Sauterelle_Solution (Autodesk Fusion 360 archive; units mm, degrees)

design "Sauterelle" references "Axe_Placage", "Embase", "Poignee", "Axe", "Support_placage", "Bielette"
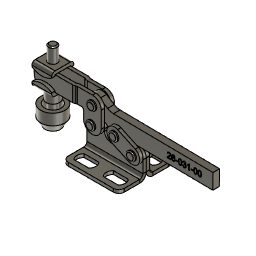
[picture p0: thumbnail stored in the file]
parameter "d13" = 1.5
parameter "d14" = 1.5
parameter "d40" = 1.5
component_insert "Insertion d'un composant1"
ground "Terre1"
component_insert "Insertion d'un composant2"
component_insert "Insertion d'un composant3"
component_insert "Insertion d'un composant4"
component_insert "Insertion d'un composant5"
component_insert "Insertion d'un composant6"
component_insert "Insertion d'un composant7"
component_insert "Insertion d'un composant8"
joint "Assembler1" alignAngle 0 alignOffsetX 0 alignOffsetY 0 alignOffsetZ 0
joint "Assembler2" alignAngle 0 alignOffsetX 0 alignOffsetY 0 alignOffsetZ 0
joint "Assembler3" alignAngle 0 alignOffsetX 0 alignOffsetY 0 alignOffsetZ 0
work_axis "Axe de construction1"
work_axis "Axe de construction2"
work_plane "Plan de construction3"
work_plane "Plan de construction1" AlongDistance -15.5 (= "( -31 / 2 ) * 1 mm")
sketch "Esquisse1" plane through (-24.25, -2.25, 16.25) normal (1, 0, 0) x axis (0, 1, 0)
  line L1 (5.75, 0.75) -> (4.25, 0.75)
  line L2 (5.75, 7.75) -> (5.75, 0.75)
  line L3 (4.25, 7.75) -> (5.75, 7.75)
  line L4 (5.75, 7.75) -> (5.75, 5.75)
  line L5 (-1.25, 7.75) -> (5.75, 7.75)
  line L6 (-1.25, 5.75) -> (-1.25, 7.75)
  line L7 (0.75, 13.9643) -> (0.75, 7.0307)
  line L8 (3.75, 7.0307) -> (3.75, 13.9643)
  line L9 (2.25, 14.1414) -> (2.25, 7.75)
  point P6 (5.75, 5.75)
  point P5 (5.75, 7.75)
  point P7 (5.75, 7.75)
  point P8 (5.75, 7.75)
  point P11 (-1.25, 5.75)
  point P9 (-1.25, 7.75)
  point P10 (-1.25, 7.75)
  point P16 (2.25, 7.75)
  coincident L2 P6
  coincident P5 P7
  perpendicular L3 L4
  coincident P5 P8
  perpendicular L5 L6
  horizontal P6 P11
  coincident P9 P10
  midpoint L5 P16
  perpendicular L5 L9
  dimension "d16" distance P6 L5 = 2
extrude "Extrusion1" new body distance 9 Side1WallThickness 1.5
fillet "Congé" radius 1.5
sketch "Esquisse2" plane through (0, -5, 0) normal (0, -1, 0) x axis (1, 0, 0)
  line L1 (-28.75, 24) -> (-19.75, 24)
  line L2 (-28.75, 22) -> (-28.75, 24)
  line L3 (-19.75, 22) -> (-28.75, 22)
  line L4 (-19.75, 24) -> (-19.75, 22)
  circle C1 centre (-24.25, 30) radius 8
  point P7 (-24.25, 22)
  point P6 (-24.25, 30)
  tangent L3 C1
  midpoint L3 P7
  vertical P6 P7
  dimension "d22" diameter C1 = 16
extrude "Extrusion2" sketch "Esquisse2" profile of L1 L2 L4 C1 no distance stored
sketch "Esquisse3" plane through (0, 0, 25.5) normal (0, 0, 1) x axis (-1, 0, 0)
  line L1 (28.75, -3.5) -> (19.75, -3.5)
  line L2 (28.75, 3.5) -> (28.75, -3.5)
  line L3 (19.75, 3.5) -> (28.75, 3.5)
  line L4 (19.75, -3.5) -> (19.75, 3.5)
  line L5 (19.75, 3.5) -> (28.75, -3.5)
  point P3 (28.75, -3.5)
  point P6 (28.75, -3.5)
  point P5 (19.75, 3.5)
  point P7 (19.75, 3.5)
  point P8 (24.25, 0)
  coincident P3 P6
  coincident P5 P7
  midpoint L5 P8
hole "Perçage" HoleDepth 3.23 HoleDiameter 4 TipAngle 180
work_plane "Plan de construction2"
mirror "Symétrie miroir" mirrorStitchTolerance 0.1
sketch "Esquisse4" plane through (0, 0, 15.5) normal (0, 0, -1) x axis (1, 0, 0)
  line L1 (-19.75, -3.5) -> (-28.75, -3.5)
  line L2 (-19.75, 3.5) -> (-19.75, -3.5)
  line L3 (-28.75, 3.5) -> (-19.75, 3.5)
  line L4 (-28.75, -3.5) -> (-28.75, 3.5)
  circle C1 centre (-24.25, 0) radius 2
  circle C2 centre (-24.25, 0) radius 3
  concentric C1 C2
  dimension "d29" diameter C2 = 6
extrude "Extrusion3" add sketch "Esquisse4" profile of C1 C2 along normal blind 5
thread "Filetage"
component_from_bodies "Corps->Comp1"
component_from_bodies "Corps->Comp2"
component_insert "Insertion d'un composant9"
base_feature "Fonction de base1"
joint "Assembler23" alignAngle 0 alignOffsetX 0 alignOffsetY 0 alignOffsetZ 0
joint "Assembler24" alignAngle 0 alignOffsetX 0 alignOffsetY 0 alignOffsetZ 0 DistanceMinimum -12.5 DistanceMaximum -5.5
joint "Assembler25" alignAngle 0 alignOffsetX 0 alignOffsetY 0 alignOffsetZ 0 AngleRest 0
motion_link "MotionLink7" Value1 10 Value2 360
joint "Assembler26" alignAngle 0 alignOffsetX 0 alignOffsetY 0 alignOffsetZ 0
joint "Assembler27" alignAngle 0 alignOffsetX 0 alignOffsetY 0 alignOffsetZ 0
joint "Assembler28" alignAngle 0 alignOffsetX 0 alignOffsetY 0 alignOffsetZ 0
component_insert "Insertion d'un composant11"
joint "Assembler29" alignAngle 0 alignOffsetX 0 alignOffsetY 0 alignOffsetZ 0
joint "Assembler30" alignAngle 0 alignOffsetX 0 alignOffsetY 0 alignOffsetZ 0
joint "Assembler31" alignAngle 0 alignOffsetX 0 alignOffsetY 0 alignOffsetZ 0
mirror_component "MirrorComponent2"
derived_instance "DerivedInstance10"
derived_instance "DerivedInstance11"
derived_instance "DerivedInstance1"
derived_instance "DerivedInstance1"
ground "Terre22"
as_built_joint "Réelle"
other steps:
step "Āᶇ    ́   Ā䣧乸攝햽␀ 䔀㌰㠷䔴ⵄ䔵㤱㐭ㅅⴴ㥂㉆㌭あ〷㜱㄰䌸D谁    Ā    硈ᵎ뵥Õ$ 〹䘴㠸䔵䐭㔸ⴹ㜴㔵䄭䔷ⵆ䔶䕂㡄㌷䘲䑁Ā"
derived_base_feature "Fonction de base dérivée1"
derived_base_feature "Fonction de base dérivée1"
derived_base_feature "Fonction de base dérivée1"
base_feature "Fonction de base1"
base_feature "Fonction de base1"
create_component "CreateComponent4"
remove_body "RemoveBody1"
create_component "CreateComponent5"
remove_body "RemoveBody2"
create_component "CreateComponent6"
joint_origin "JointOrigin2"
joint_origin "JointOrigin4"
joint_origin "JointOrigin3"
create_component "CreateComponent17"
create_component "CreateComponent18"
create_component "CreateComponent19"

design "Squelette"
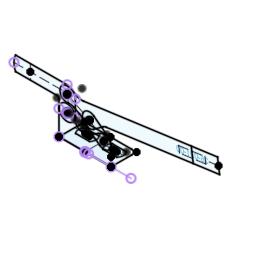
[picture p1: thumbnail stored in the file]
parameter "d71" = 3 (= "Linear Dimension-10")
sketch "Esquisse1" plane through (0, 0, 0) normal (0, 0, 1) x axis (1, 0, 0)
  line L1 (12.75, 0) -> (-12.75, 0)
  line L2 (-12.75, 10) -> (-12.75, 0)
  line L3 (10.25, 12.5) -> (-10.25, 12.5)
  line L4 (12.75, 0) -> (12.75, 10)
  line L5 (12.75, 7.8) -> (-12.75, 7.8)
  line L6 (0, 0) -> (0, 12.5)
  line L7 (-3.3038, 5.5) -> (-10.0462, 5.5)
  line L8 (-10.0462, 10.1) -> (-3.3038, 10.1)
  line L9 (-5.6, 7.8) -> (-7.75, 7.8)
  line L10 (10.0462, 10.1) -> (3.3038, 10.1)
  line L11 (3.3038, 5.5) -> (10.0462, 5.5)
  line L12 (7.75, 7.8) -> (5.6, 7.8)
  arc A1 centre (-5.6, 7.8) radius 3.25 clockwise from (-3.3038, 10.1) to (-3.3038, 5.5)
  arc A2 centre (-7.75, 7.8) radius 3.25 clockwise from (-10.0462, 5.5) to (-10.0462, 10.1)
  arc A3 centre (7.75, 7.8) radius 3.25 clockwise from (10.0462, 10.1) to (10.0462, 5.5)
  arc A4 centre (5.6, 7.8) radius 3.25 clockwise from (3.3038, 5.5) to (3.3038, 10.1)
  arc A5 centre (-10.25, 10) radius 2.5 clockwise from (-12.75, 10) to (-10.25, 12.5)
  arc A6 centre (10.25, 10) radius 2.5 clockwise from (10.25, 12.5) to (12.75, 10)
  point P4 (0, 0)
  point P1 (0, 0)
  point P5 (-12.75, 0)
  point P8 (12.75, 0)
  point P9 (0, 12.5)
  point P10 (-12.75, 7.8)
  point P11 (12.75, 7.8)
  point P12 (0, 12.5)
  point P13 (0, 0)
  point P19 (-5.6, 7.8)
  point P14 (-10.0462, 5.5)
  point P23 (10.0462, 5.5)
  point P15 (-3.3038, 5.5)
  point P25 (3.3038, 5.5)
  point P16 (-3.3038, 10.1)
  point P20 (3.3038, 10.1)
  point P17 (-10.0462, 10.1)
  point P21 (10.0462, 10.1)
  point P26 (-6.675, 7.8)
  point P27 (6.675, 7.8)
  point P24 (5.6, 7.8)
  point P28 (5.6, 7.8)
  point P22 (7.75, 7.8)
  point P29 (7.75, 7.8)
  point P30 (6.675, 7.8)
  point P2 (-12.75, 0)
  point P6 (-12.75, 12.5)
  point P7 (12.75, 12.5)
  point P3 (12.75, 0)
  point P18 (-7.75, 7.8)
  horizontal L1
  midpoint L1 P4
  coincident P1 P4
  coincident L1 P5
  perpendicular L1 L2
  perpendicular L2 L3
  coincident L1 P8
  perpendicular L1 L4
  vertical P1 P9
  coincident L2 P10
  coincident L4 P11
  perpendicular L4 L5
  coincident P9 P12
  coincident P4 P13
  parallel L7 L8
  coincident L5 P19
  parallel L5 L9
  symmetric L6 P14 P23
  symmetric L6 P15 P25
  symmetric L6 P16 P20
  symmetric L6 P17 P21
  symmetric L6 A1 A4
  symmetric L6 A2 A3
  midpoint L9 P26
  coincident L5 P27
  coincident P24 P28
  coincident P22 P29
  midpoint L12 P30
  coincident P27 P30
  horizontal L8
  equal A1 A2
  symmetric L5 L7 L8
  coincident P2 L2
  coincident L3 P9
  coincident P6 L3
  coincident P6 L2
  tangent L3 A5
  tangent L2 A5
  coincident P7 L3
  coincident P7 L4
  tangent L3 A6
  tangent L4 A6
  equal A5 A6
  coincident P3 L4
  dimension "L10" = 15.6
  dimension "L8" distance L2 P18 = 5
  dimension "L12" distance P6 P7 = 25.5
  dimension "L30" = 25
  dimension "d1" distance L7 L8 = 4.6
  dimension "d10" radius A2 = 3.25 (= "( 6.5 / 2 ) * 1 mm")
  dimension "d11" distance P19 P24 = 11.2
  dimension "d12" radius A5 = 2.5
sketch "Esquisse3" plane through (0, 0, 0) normal (0, 1, 0) x axis (1, 0, 0)
  line L1 (-12.75, -12) -> (-12.75, 0)
  line L2 (12.75, 0) -> (12.75, -8.5)
  line L3 (0.0442, -8) -> (-1.75, -8)
  line L4 (7.5, -11.5311) -> (2.5442, -8.6699)
  line L5 (-4.75, -11) -> (-4.75, -12)
  line L6 (12.75, 0) -> (-12.75, 0)
  line L7 (12.75, 0) -> (-12.75, 0)
  arc A1 centre (-8.75, -12) radius 4 clockwise from (-4.75, -12) to (-12.75, -12)
  arc A2 centre (9.25, -8.5) radius 3.5 clockwise from (12.75, -8.5) to (7.5, -11.5311)
  arc A3 centre (-1.75, -11) radius 3 clockwise from (-4.75, -11) to (-1.75, -8)
  circle C1 centre (-8.75, -12.5) radius 1.25
  circle C2 centre (9.25, -9.2) radius 1.25
  arc A4 centre (0.0442, -13) radius 5 clockwise from (0.0442, -8) to (2.5442, -8.6699)
  point P2 (-12.75, 0)
  point P4 (-12.75, 0)
  point P3 (12.75, 0)
  point P7 (12.75, 0)
  point P20 (12.75, 0)
  point P25 (12.75, -4.25)
  point P9 (-8.75, -12)
  point P15 (-8.75, -12.5)
  point P12 (9.25, -8.5)
  point P16 (9.25, -9.2)
  coincident P2 P4
  vertical L1
  coincident P3 P7
  vertical L2
  tangent L1 A1
  perpendicular L1 L3
  tangent L4 A2
  vertical L5
  tangent L5 A3
  tangent A1 L5
  tangent L3 A3
  tangent L2 A2
  equal C1 C2
  tangent L3 A4
  tangent L4 A4
  coincident P3 P20
  midpoint L2 P25
  vertical P9 P15
  vertical P12 P16
  dimension "d13" diameter C1 = 2.5
  dimension "d14" distance P9 P16 = 18
  dimension "d17" distance P15 P16 = 3.3
  dimension "d18" radius A1 = 4
  dimension "d19" distance L3 L7 = 8
  dimension "d20" radius A3 = 3
  dimension "d21" angle L4 L7 = 30
  dimension "d22" radius A4 = 5
  dimension "d65" distance P9 L6 = 12
  dimension "d66" distance P9 P15 = 0.5
  dimension "d67" distance P12 P16 = 0.7
sketch "Esquisse4" plane through (0, 0, 0) normal (0, 1, 0) x axis (1, 0, 0)
  line L1 (-8.75, -24) -> (-33.9437, -24)
  line L2 (-33.9437, -17) -> (-13.75, -17)
  line L3 (-26.75, -17) -> (-26.75, -24)
  line L4 (-4.75, -12.5) -> (-4.75, -20)
  line L5 (-12.75, -16) -> (-12.75, -12.5)
  line L6 (-8.75, -20.5) -> (-34.75, -20.5)
  arc A1 centre (-26.75, -20.5) radius 8 clockwise from (-33.9437, -24) to (-33.9437, -17)
  arc A2 centre (-13.75, -16) radius 1 clockwise from (-12.75, -16) to (-13.75, -17)
  arc A3 centre (-8.75, -20) radius 4 clockwise from (-4.75, -20) to (-8.75, -24)
  arc A4 centre (-8.75, -12.5) radius 4 clockwise from (-12.75, -12.5) to (-4.75, -12.5)
  circle C1 centre (-8.75, -20) radius 1.25
  circle C2 centre (-8.75, -12.5) radius 1.25
  arc A5 centre (-8.75, -12) radius 4 clockwise from (-4.75, -12) to (-12.75, -12)
  point P5 (-26.75, -24)
  point P6 (-26.75, -17)
  point P10 (-26.75, -20.5)
  point P22 (-34.75, -20.5)
  point P4 (-8.75, -20)
  point P23 (-8.75, -20.5)
  point P3 (-8.75, -12.5)
  point P16 (-8.75, -20)
  point P18 (0, 0)
  horizontal L1
  tangent L1 A3
  perpendicular L1 L4
  tangent L4 A4
  tangent A2 L5
  perpendicular L2 L5
  tangent A4 L5
  tangent A3 L4
  equal A3 A4
  tangent L2 A2
  coincident P5 L1
  coincident P6 L2
  perpendicular L2 L3
  midpoint P10 L3
  concentric A3 C1
  concentric A4 C2
  equal C1 C2
  equal A3 A5
  midpoint A1 P22
  perpendicular L3 L6
  vertical P4 P23
  dimension "d35" distance P3 P16 = 7.5
  dimension "d36" distance L1 L2 = 7
  dimension "d38" radius A1 = 8
  dimension "d39" radius A2 = 1
  dimension "h1" distance L2 P18 = 17
  dimension "d72" distance P22 P23 = 26
sketch "Esquisse5" plane through (0, 0, 0) normal (0, 1, 0) x axis (1, 0, 0)
  line L1 (-0.7878, -21.1048) -> (64.8602, -30.2143)
  line L2 (-7.3208, -23.1949) -> (-3.5167, -21.4932)
  line L3 (-2.723, -14.7333) -> (-5.627, -16.1925)
  line L4 (8.892, -15.0264) -> (4.2482, -11.6649)
  line L5 (65.8223, -23.2807) -> (10.2388, -15.5678)
  line L6 (64.8602, -30.2143) -> (65.8223, -23.2807)
  line L7 (22.5, 0) -> (1.75, 0)
  line L8 (-8.1307, -16.5552) -> (-8.75, -20)
  line L9 (2.1959, -14.5) -> (-8.75, -20)
  curve K1
  curve K2
  curve K3
  curve K4
  line L10 (58.9029, -25.8541) -> (65.3412, -26.7475)
  line L11 (52.9457, -21.4939) -> (51.9836, -28.4275)
  arc A1 centre (-1.475, -26.0574) radius 5 clockwise from (-3.5167, -21.4932) to (-0.7878, -21.1048)
  arc A2 centre (-8.75, -20) radius 3.5 clockwise from (-7.3208, -23.1949) to (-8.1307, -16.5552)
  arc A3 centre (-7.4229, -12.6183) radius 4 clockwise from (-5.627, -16.1925) to (-8.1307, -16.5552)
  arc A4 centre (-4.5189, -11.1592) radius 4 clockwise from (-0.9377, -12.9409) to (-2.723, -14.7333)
  arc A5 centre (2.1959, -14.5) radius 3.5 clockwise from (-0.9377, -12.9409) to (4.2482, -11.6649)
  arc A6 centre (10.6512, -12.5963) radius 3 clockwise from (10.2388, -15.5678) to (8.892, -15.0264)
  arc A7 centre (-8.75, -20) radius 4 clockwise from (-4.75, -20) to (-8.75, -24)
  circle C1 centre (-8.75, -20) radius 1.25
  circle C2 centre (2.1959, -14.5) radius 1.25
  point P8 (-8.75, -20)
  point P28 (-8.75, -20)
  point P23 (-8.75, -20)
  point P29 (-8.75, -20)
  point P15 (2.1959, -14.5)
  point P30 (2.1959, -14.5)
  point P32 (65.3412, -26.7475)
  point P34 (65.3412, -26.7475)
  point P35 (58.9029, -25.8541)
  point P36 (51.9836, -28.4275)
  point P37 (52.9457, -21.4939)
  point P2 (64.8602, -30.2143)
  point P19 (65.8223, -23.2807)
  point P33 (-34.75, -20.5)
  point P24 (-8.75, -20)
  point P31 (-8.75, -12)
  tangent L1 A1
  tangent A1 L2
  tangent L2 A2
  tangent A2 A3
  tangent A3 L3
  tangent L3 A4
  tangent A4 A5
  tangent A5 L4
  tangent L4 A6
  parallel L1 L5
  perpendicular L1 L6
  tangent A6 L5
  concentric A2 A7
  equal A2 A5
  concentric A5 C2
  equal C1 C2
  coincident L1 P8
  equal A3 A4
  coincident P8 P28
  coincident P23 P29
  coincident P15 P30
  parallel L3 L9
  midpoint L6 P32
  parallel L1 K3
  coincident P32 P34
  midpoint K4 P35
  parallel L1 L10
  coincident L1 P36
  coincident L5 P37
  perpendicular L5 L11
  coincident L11
  dimension "d41" distance P2 P19 = 7
  dimension "d42" radius A1 = 5
  dimension "d43" angle L1 L2 = 148
  dimension "L3" distance L6 P33 = 100
  dimension "d46" distance P15 P24 = 12.25
  dimension "d47" radius A2 = 3.5
  dimension "d48" angle L1 L7 = 7.9
  dimension "d49" radius A6 = 3
  dimension "d50" radius A3 = 4
  dimension "d51" angle L1 L4 = 28
  dimension "d52" distance P15 L7 = 14.5
  dimension "d53" distance L3 L9 = 2
  dimension "d64" distance P29 P31 = 8
  dimension "d74" = 13
  dimension "d73" Text1-Height = 2.5
  dimension "d75" distance = 13
  dimension "d76" distance = 3
sketch "Esquisse6" plane through (0, 0, 0) normal (0, 1, 0) x axis (1, 0, 0)
  line L1 (11.3524, -11.9982) -> (4.2983, -17.2982)
  line L2 (0.0935, -11.7018) -> (7.1476, -6.4018)
  line L3 (9.25, -9.2) -> (2.1959, -14.5)
  circle C1 centre (2.1959, -14.5) radius 1.25
  circle C2 centre (9.25, -9.2) radius 1.25
  arc A1 centre (9.25, -9.2) radius 3.5 clockwise from (7.1476, -6.4018) to (11.3524, -11.9982)
  arc A2 centre (2.1959, -14.5) radius 3.5 clockwise from (4.2983, -17.2982) to (0.0935, -11.7018)
  point P3 (9.25, -9.2)
  point P9 (9.25, -9.2)
  point P2 (2.1959, -14.5)
  point P8 (2.1959, -14.5)
  tangent L1 A1
  tangent A1 L2
  parallel L1 L2
  tangent L2 A2
  tangent L1 A2
  coincident P3 P9
  coincident P2 P8
  dimension "d54" radius A1 = 3.5
work_plane "Plan de construction8" AlongDistance 1.5 named "Ep"
work_plane "Plan de construction16" AlongDistance 3.5 (= "2 * Ep + 0.5 mm")
work_plane "Plan de construction17"
work_plane "Plan de construction18" AlongDistance 3 (= "2 * Ep")
work_plane "Plan de construction19" AlongDistance 4 (= "2 * Ep + 1 mm")

design "Axe_Placage"
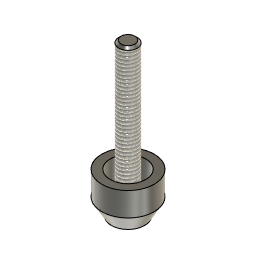
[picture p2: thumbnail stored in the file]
sketch "Esquisse" plane through (0, 0, 0) normal (0, 1, 0) x axis (1, 0, 0)
  line L1 (0, -32) -> (0, 0)
  line L2 (2, -32) -> (0, -32)
  line L3 (2, -8.5) -> (2, -32)
  line L4 (5.5, -8.5) -> (2, -8.5)
  line L5 (5.5, -3.5) -> (5.5, -8.5)
  line L6 (3.5, 0) -> (5.5, -3.5)
  line L7 (0, 0) -> (3.5, 0)
  line L8 (2, -3.5) -> (2, -8.5)
  line L9 (3.75, -3.5) -> (2, -3.5)
  line L10 (3.75, -8.5) -> (3.75, -3.5)
  point P1 (0, 0)
  point P2 (0, 0)
  point P9 (0, 0)
  point P3 (0, -32)
  point P6 (5.5, -8.5)
  point P7 (5.5, -3.5)
  coincident P1 P2
  vertical L1
  perpendicular L1 L2
  perpendicular L2 L3
  perpendicular L3 L4
  perpendicular L4 L5
  coincident P1 P9
  perpendicular L1 L7
  perpendicular L4 L8
  perpendicular L3 L9
  perpendicular L4 L10
  dimension "d1" distance P2 P3 = 32
  dimension "d2" = 11
  dimension "d3" = 7
  dimension "d4" distance P6 P7 = 5
  dimension "d5" distance L4 L7 = 8.5
  dimension "d6" = 4
  dimension "d10" = 7.5
  dimension "d11" distance L4 L9 = 5
revolve "Révolution" sketch "Esquisse" AlongAngle 360
thread "Filetage"
chamfer "Chanfrein" distance 0.5

design "Axe" references "Squelette"
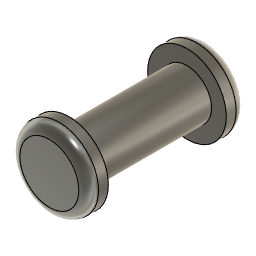
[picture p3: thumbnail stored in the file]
component_insert "Insertion d'un composant"
ground "Terre"
extrude "Extrusion1" new body to an object
sketch "Esquisse" plane through (0, 4, 0) normal (0, 1, 0) x axis (-1, 0, 0)
  circle C1 centre (-9.25, 9.2) radius 1.25
  circle C2 centre (-9.25, 9.2) radius 2
  concentric C1 C2
  dimension "d3" diameter C2 = 4
extrude "Extrusion2" add sketch "Esquisse" against normal blind 1
fillet "Congé" radius 0.5
mirror "Symétrie miroir" mirrorStitchTolerance 0.1

design "Bielette" references "Squelette"
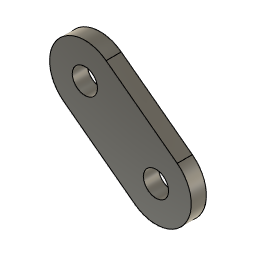
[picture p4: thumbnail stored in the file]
parameter "d4" = 1.5
component_insert "Insertion d'un composant"
ground "Terre"
extrude "Extrusion" to an object
step "Convertir en tôle"

design "Poignee" references "Squelette"
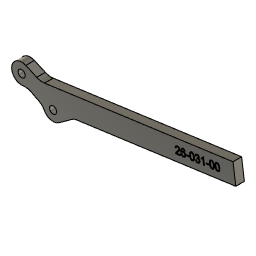
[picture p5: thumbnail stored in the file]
parameter "d4" = 3
component_insert "Insertion d'un composant"
ground "Terre"
extrude "Extrusion1" to an object
step "Convertir en tôle"
extrude "Extrusion2" cut blind 0.5 from offset 1
circular_pattern "Réseau C" TotalAngle 360

design "Support_placage" references "Squelette"
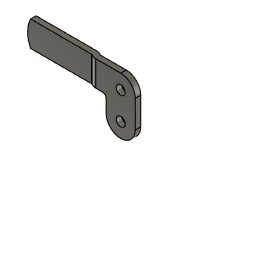
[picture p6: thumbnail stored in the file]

design "Embase" references "Squelette"
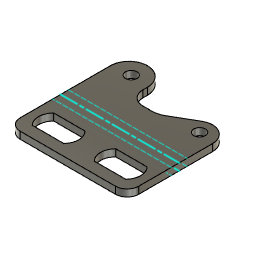
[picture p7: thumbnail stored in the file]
parameter "d3" = 1.5
component_insert "Insertion d'un composant"
ground "Terre"
extrude "Extrusion1" new body to an object
step "Convertir en tôle"
face "Bord tombé d'arête" FlangeHeight 22 FlangeAngle 90
extrude "Extrusion2" no distance stored
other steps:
step "ഁ"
